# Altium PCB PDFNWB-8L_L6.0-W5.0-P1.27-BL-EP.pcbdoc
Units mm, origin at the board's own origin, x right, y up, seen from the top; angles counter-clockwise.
Board outline 17.98 x 20.21 mm, 2 copper layers (Top Layer, Bottom Layer), stack 0 mm thick; 1 components, 0 nets, 9 pads, 0 vias.
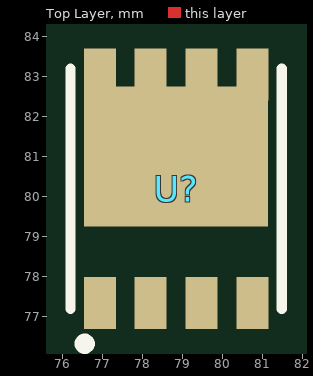
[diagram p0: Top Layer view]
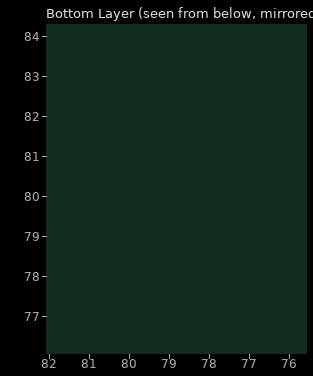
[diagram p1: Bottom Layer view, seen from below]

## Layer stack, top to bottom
Top Layer: signal copper (thickness not stored)
Bottom Layer: signal copper (thickness not stored)

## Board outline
87.83,69.85 69.85,69.85 69.85,90.058 87.83,90.058

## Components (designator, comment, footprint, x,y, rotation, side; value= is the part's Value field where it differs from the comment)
U? "" PDFNWB-8L_L6.0-W5.0-P1.27-BL-EP 78.84,80.2 r0 top

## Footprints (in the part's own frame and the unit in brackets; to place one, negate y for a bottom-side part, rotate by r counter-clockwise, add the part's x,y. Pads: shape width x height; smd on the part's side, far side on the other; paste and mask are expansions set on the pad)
PDFNWB-8L_L6.0-W5.0-P1.27-BL-EP [mm]
  rect 0.8x1.3 smd paste-100 mask+0.051: 1(-1.905,-2.857) 2(-0.635,-2.857) 3(0.635,-2.857) 4(1.905,-2.857) 5(1.905,2.857) 6(0.635,2.857) 7(-0.635,2.857) 8(-1.905,2.857)
  rect 4.6x3.5 smd paste-100 mask+0.051: 8(0,0.813)
  silkscreen extent -2.64,-4 2.64,3

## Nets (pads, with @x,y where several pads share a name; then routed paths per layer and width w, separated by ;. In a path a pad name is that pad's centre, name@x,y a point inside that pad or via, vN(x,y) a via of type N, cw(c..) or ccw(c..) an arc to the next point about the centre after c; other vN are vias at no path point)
pads on no net: U?.1 U?.2 U?.3 U?.4 U?.5 U?.6 U?.7 U?.8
